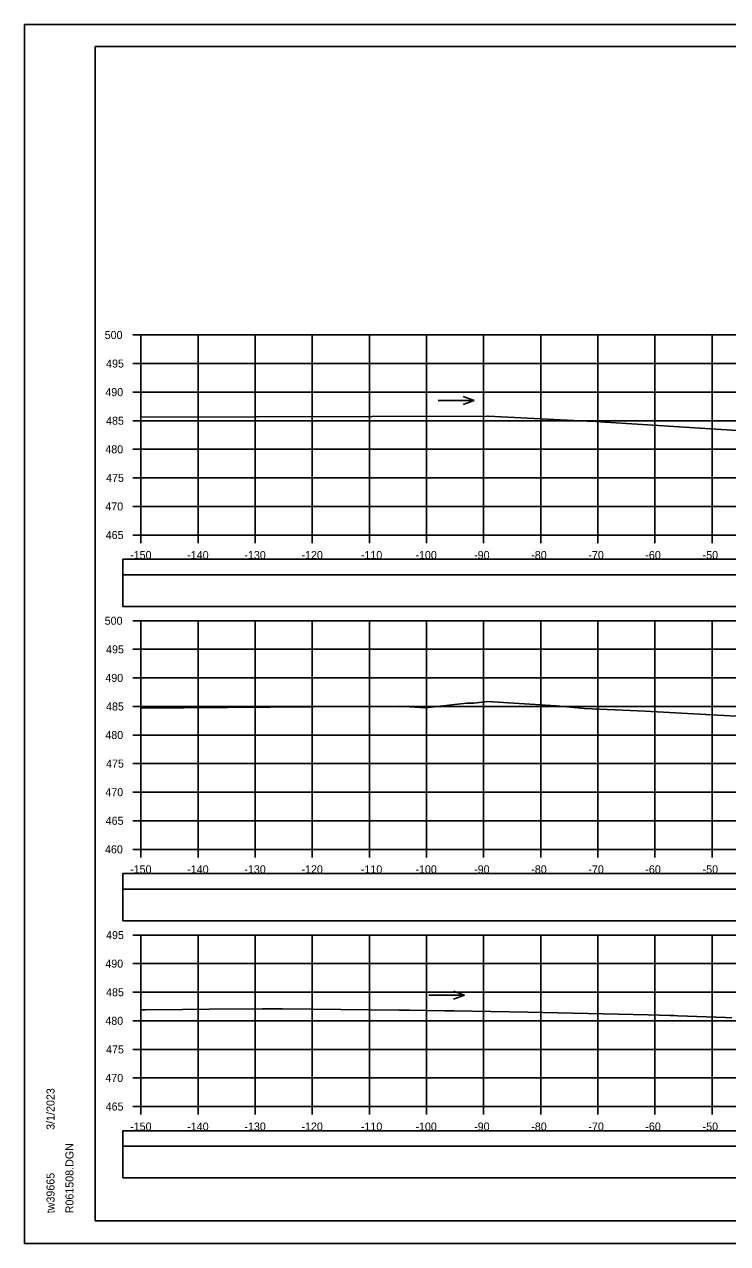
# Model space of a CAD drawing. Extents: x 1371057 to 1372761, y 380005 to 390517.
# Drawn here: x 1371390.5 to 1371513.6, y 380431.8 to 380645.1 of the extents above; entities that cross this region are included whole.
import ezdxf

# ---------------------------------------------------------------- set-up
doc = ezdxf.new("R2010")
doc.units = 0
for name, color, linetype in [('R_Axis', 7, 'Continuous'), ('R_Axis Annot', 7, 'Continuous'), ('R_Border', 7, 'Continuous'), ('R_Detour', 7, 'Continuous'), ('R_Dimension', 7, 'Continuous'), ('R_Exist Surface', 7, 'Continuous'), ('R_Grid', 7, 'Continuous'), ('R_No Plot', 7, 'Continuous'), ('R_Water Annot', 7, 'Continuous')]:
    doc.layers.add(name, color=color, linetype=linetype)

msp = doc.modelspace()

# ---------------------------------------------------------------- linework, layer by layer
at = {"layer": 'R_Axis'}
for p, q in [((1371409.47, 380590.74), (1371410.87, 380590.74)), ((1371410.87, 380555.74), (1371410.87, 380590.74)), ((1371409.47, 380585.74), (1371410.87, 380585.74)), ((1371409.47, 380580.74), (1371410.87, 380580.74)), ((1371409.47, 380575.74), (1371410.87, 380575.74)), ((1371409.47, 380570.74), (1371410.87, 380570.74)), ((1371409.47, 380565.74), (1371410.87, 380565.74)), ((1371409.47, 380560.74), (1371410.87, 380560.74)), ((1371409.47, 380555.74), (1371410.87, 380555.74)), ((1371410.87, 380555.74), (1371710.87, 380555.74)), ((1371410.87, 380554.34), (1371410.87, 380555.74)), ((1371420.87, 380554.34), (1371420.87, 380555.74)), ((1371430.87, 380554.34), (1371430.87, 380555.74)), ((1371440.87, 380554.34), (1371440.87, 380555.74)), ((1371450.87, 380554.34), (1371450.87, 380555.74)), ((1371460.87, 380554.34), (1371460.87, 380555.74)), ((1371470.87, 380554.34), (1371470.87, 380555.74)), ((1371480.87, 380554.34), (1371480.87, 380555.74)), ((1371490.87, 380554.34), (1371490.87, 380555.74)), ((1371500.87, 380554.34), (1371500.87, 380555.74)), ((1371510.87, 380554.34), (1371510.87, 380555.74)), ((1371409.47, 380540.74), (1371410.87, 380540.74)), ((1371410.87, 380500.74), (1371410.87, 380540.74)), ((1371409.47, 380535.74), (1371410.87, 380535.74)), ((1371409.47, 380530.74), (1371410.87, 380530.74)), ((1371409.47, 380525.74), (1371410.87, 380525.74)), ((1371409.47, 380520.74), (1371410.87, 380520.74)), ((1371409.47, 380515.74), (1371410.87, 380515.74)), ((1371409.47, 380510.74), (1371410.87, 380510.74)), ((1371409.47, 380505.74), (1371410.87, 380505.74)), ((1371409.47, 380500.74), (1371410.87, 380500.74)), ((1371410.87, 380500.74), (1371710.87, 380500.74)), ((1371410.87, 380499.34), (1371410.87, 380500.74)), ((1371420.87, 380499.34), (1371420.87, 380500.74)), ((1371430.87, 380499.34), (1371430.87, 380500.74)), ((1371440.87, 380499.34), (1371440.87, 380500.74)), ((1371450.87, 380499.34), (1371450.87, 380500.74)), ((1371460.87, 380499.34), (1371460.87, 380500.74)), ((1371470.87, 380499.34), (1371470.87, 380500.74)), ((1371480.87, 380499.34), (1371480.87, 380500.74)), ((1371490.87, 380499.34), (1371490.87, 380500.74)), ((1371500.87, 380499.34), (1371500.87, 380500.74)), ((1371510.87, 380499.34), (1371510.87, 380500.74)), ((1371409.47, 380485.74), (1371410.87, 380485.74)), ((1371410.87, 380455.74), (1371410.87, 380485.74)), ((1371409.47, 380480.74), (1371410.87, 380480.74)), ((1371409.47, 380475.74), (1371410.87, 380475.74)), ((1371409.47, 380470.74), (1371410.87, 380470.74)), ((1371409.47, 380465.74), (1371410.87, 380465.74)), ((1371409.47, 380460.74), (1371410.87, 380460.74)), ((1371409.47, 380455.74), (1371410.87, 380455.74)), ((1371410.87, 380455.74), (1371710.87, 380455.74)), ((1371410.87, 380454.34), (1371410.87, 380455.74)), ((1371420.87, 380454.34), (1371420.87, 380455.74)), ((1371430.87, 380454.34), (1371430.87, 380455.74)), ((1371440.87, 380454.34), (1371440.87, 380455.74)), ((1371450.87, 380454.34), (1371450.87, 380455.74)), ((1371460.87, 380454.34), (1371460.87, 380455.74)), ((1371470.87, 380454.34), (1371470.87, 380455.74)), ((1371480.87, 380454.34), (1371480.87, 380455.74)), ((1371490.87, 380454.34), (1371490.87, 380455.74)), ((1371500.87, 380454.34), (1371500.87, 380455.74)), ((1371510.87, 380454.34), (1371510.87, 380455.74))]:
    msp.add_line(p, q, dxfattribs=at)
at = {"layer": 'R_Border'}
for p, q in [((1371402.87, 380641.2), (1371719.05, 380641.2)), ((1371402.87, 380435.74), (1371402.87, 380641.2)), ((1371402.87, 380435.74), (1371402.87, 380435.74)), ((1371719.05, 380435.74), (1371402.87, 380435.74))]:
    msp.add_line(p, q, dxfattribs=at)
at = {"layer": 'R_Detour'}
for points in [[(1371407.72, 380548.78), (1371714.03, 380548.78), (1371714.03, 380551.49), (1371407.72, 380551.49)], [(1371407.72, 380493.78), (1371714.03, 380493.78), (1371714.03, 380496.49), (1371407.72, 380496.49)], [(1371407.72, 380448.78), (1371714.03, 380448.78), (1371714.03, 380451.49), (1371407.72, 380451.49)]]:
    msp.add_lwpolyline(points, close=True, dxfattribs=at)
at = {"layer": 'R_Dimension'}
for points in [[(1371407.72, 380543.26), (1371714.03, 380543.26), (1371714.03, 380548.78), (1371407.72, 380548.78)], [(1371407.72, 380488.26), (1371714.03, 380488.26), (1371714.03, 380493.78), (1371407.72, 380493.78)], [(1371407.72, 380443.26), (1371714.03, 380443.26), (1371714.03, 380448.78), (1371407.72, 380448.78)]]:
    msp.add_lwpolyline(points, close=True, dxfattribs=at)
at = {"layer": 'R_Exist Surface'}
for points in [[(1371410.87, 380576.35), (1371471.57, 380576.55), (1371471.64, 380576.56), (1371471.64, 380576.55), (1371488.92, 380575.69), (1371489.48, 380575.65), (1371515.19, 380574.03)], [(1371410.87, 380525.47), (1371456.22, 380525.78), (1371460.64, 380525.53), (1371467.92, 380526.31), (1371469.14, 380526.31), (1371471.03, 380526.53), (1371471.55, 380526.63), (1371483.58, 380525.83), (1371488.55, 380525.4), (1371499.14, 380524.91), (1371515.1, 380524.03)], [(1371410.87, 380472.66), (1371411.74, 380472.67), (1371418.14, 380472.74), (1371422.8, 380472.79), (1371432.16, 380472.86), (1371435.63, 380472.83), (1371456.12, 380472.61), (1371457.88, 380472.59), (1371464.04, 380472.49), (1371465.65, 380472.46), (1371478.62, 380472.26), (1371497.08, 380471.82), (1371499.7, 380471.77), (1371503.52, 380471.67), (1371504.29, 380471.64), (1371504.87, 380471.62), (1371513.22, 380471.33), (1371514.33, 380471.26)]]:
    msp.add_lwpolyline(points, dxfattribs=at)
at = {"layer": 'R_Grid'}
for p, q in [((1371410.87, 380590.74), (1371710.87, 380590.74)), ((1371410.87, 380555.74), (1371410.87, 380590.74)), ((1371420.87, 380555.74), (1371420.87, 380590.74)), ((1371430.87, 380555.74), (1371430.87, 380590.74)), ((1371440.87, 380555.74), (1371440.87, 380590.74)), ((1371450.87, 380555.74), (1371450.87, 380590.74)), ((1371460.87, 380555.74), (1371460.87, 380590.74)), ((1371470.87, 380555.74), (1371470.87, 380590.74)), ((1371480.87, 380555.74), (1371480.87, 380590.74)), ((1371490.87, 380555.74), (1371490.87, 380590.74)), ((1371500.87, 380555.74), (1371500.87, 380590.74)), ((1371510.87, 380555.74), (1371510.87, 380590.74)), ((1371410.87, 380585.74), (1371710.87, 380585.74)), ((1371410.87, 380580.74), (1371710.87, 380580.74)), ((1371410.87, 380575.74), (1371710.87, 380575.74)), ((1371410.87, 380570.74), (1371710.87, 380570.74)), ((1371410.87, 380565.74), (1371710.87, 380565.74)), ((1371410.87, 380560.74), (1371710.87, 380560.74)), ((1371410.87, 380555.74), (1371710.87, 380555.74)), ((1371410.87, 380540.74), (1371710.87, 380540.74)), ((1371410.87, 380500.74), (1371410.87, 380540.74)), ((1371420.87, 380500.74), (1371420.87, 380540.74)), ((1371430.87, 380500.74), (1371430.87, 380540.74)), ((1371440.87, 380500.74), (1371440.87, 380540.74)), ((1371450.87, 380500.74), (1371450.87, 380540.74)), ((1371460.87, 380500.74), (1371460.87, 380540.74)), ((1371470.87, 380500.74), (1371470.87, 380540.74)), ((1371480.87, 380500.74), (1371480.87, 380540.74)), ((1371490.87, 380500.74), (1371490.87, 380540.74)), ((1371500.87, 380500.74), (1371500.87, 380540.74)), ((1371510.87, 380500.74), (1371510.87, 380540.74)), ((1371410.87, 380535.74), (1371710.87, 380535.74)), ((1371410.87, 380530.74), (1371710.87, 380530.74)), ((1371410.87, 380525.74), (1371710.87, 380525.74)), ((1371410.87, 380520.74), (1371710.87, 380520.74)), ((1371410.87, 380515.74), (1371710.87, 380515.74)), ((1371410.87, 380510.74), (1371710.87, 380510.74)), ((1371410.87, 380505.74), (1371710.87, 380505.74)), ((1371410.87, 380500.74), (1371710.87, 380500.74)), ((1371410.87, 380485.74), (1371710.87, 380485.74)), ((1371410.87, 380455.74), (1371410.87, 380485.74)), ((1371420.87, 380455.74), (1371420.87, 380485.74)), ((1371430.87, 380455.74), (1371430.87, 380485.74)), ((1371440.87, 380455.74), (1371440.87, 380485.74)), ((1371450.87, 380455.74), (1371450.87, 380485.74)), ((1371460.87, 380455.74), (1371460.87, 380485.74)), ((1371470.87, 380455.74), (1371470.87, 380485.74)), ((1371480.87, 380455.74), (1371480.87, 380485.74)), ((1371490.87, 380455.74), (1371490.87, 380485.74)), ((1371500.87, 380455.74), (1371500.87, 380485.74)), ((1371510.87, 380455.74), (1371510.87, 380485.74)), ((1371410.87, 380480.74), (1371710.87, 380480.74)), ((1371410.87, 380475.74), (1371710.87, 380475.74)), ((1371410.87, 380470.74), (1371710.87, 380470.74)), ((1371410.87, 380465.74), (1371710.87, 380465.74)), ((1371410.87, 380460.74), (1371710.87, 380460.74)), ((1371410.87, 380455.74), (1371710.87, 380455.74))]:
    msp.add_line(p, q, dxfattribs=at)
at = {"layer": 'R_No Plot'}
for p, q in [((1371390.47, 380645.09), (1371723.8, 380645.09)), ((1371390.47, 380431.76), (1371723.8, 380431.76))]:
    msp.add_line(p, q, dxfattribs=at)
for points in [[(1371390.46, 380645.09), (1371723.8, 380645.09), (1371723.8, 380431.75), (1371390.46, 380431.75)], [(1371636.79, 380641.2), (1371656.41, 380641.2), (1371656.41, 380631.32), (1371672.52, 380631.32), (1371695.72, 380631.32), (1371695.84, 380603.16), (1371719.05, 380603.16), (1371719.05, 380435.74), (1371402.87, 380435.74), (1371402.87, 380641.2)]]:
    msp.add_lwpolyline(points, close=True, dxfattribs=at)
at = {"layer": 'R_Water Annot'}
for p, q in [((1371469.19, 380579.25), (1371467.27, 380579.95)), ((1371462.91, 380579.25), (1371469.19, 380579.25)), ((1371469.19, 380579.25), (1371467.27, 380578.55)), ((1371461.26, 380475.24), (1371467.55, 380475.24)), ((1371467.55, 380475.24), (1371465.62, 380475.94)), ((1371467.55, 380475.24), (1371465.62, 380474.54))]:
    msp.add_line(p, q, dxfattribs=at)

# ---------------------------------------------------------------- texts
at = {"layer": 'R_Axis Annot'}
for s, p in [('500', (1371404.53, 380590.04)), ('495', (1371404.77, 380585.04)), ('490', (1371404.64, 380580.04)), ('485', (1371404.77, 380575.04)), ('480', (1371404.64, 380570.04)), ('475', (1371404.77, 380565.04)), ('470', (1371404.64, 380560.04)), ('465', (1371404.7, 380555.04)), ('-150', (1371408.98, 380551.54)), ('-140', (1371418.98, 380551.54)), ('-130', (1371428.98, 380551.54)), ('-120', (1371438.98, 380551.54)), ('-110', (1371449.38, 380551.54)), ('-100', (1371458.93, 380551.54)), ('-90', (1371469.21, 380551.54)), ('-80', (1371479.21, 380551.54)), ('-70', (1371489.21, 380551.54)), ('-60', (1371499.18, 380551.54)), ('-50', (1371509.21, 380551.54)), ('500', (1371404.53, 380540.04)), ('495', (1371404.77, 380535.04)), ('490', (1371404.64, 380530.04)), ('485', (1371404.77, 380525.04)), ('480', (1371404.64, 380520.04)), ('475', (1371404.77, 380515.04)), ('470', (1371404.64, 380510.04)), ('465', (1371404.7, 380505.04)), ('460', (1371404.58, 380500.04)), ('-150', (1371408.98, 380496.54)), ('-140', (1371418.98, 380496.54)), ('-130', (1371428.98, 380496.54)), ('-120', (1371438.98, 380496.54)), ('-110', (1371449.38, 380496.54)), ('-100', (1371458.93, 380496.54)), ('-90', (1371469.21, 380496.54)), ('-80', (1371479.21, 380496.54)), ('-70', (1371489.21, 380496.54)), ('-60', (1371499.18, 380496.54)), ('-50', (1371509.21, 380496.54)), ('495', (1371404.77, 380485.04)), ('490', (1371404.64, 380480.04)), ('485', (1371404.77, 380475.04)), ('480', (1371404.64, 380470.04)), ('475', (1371404.77, 380465.04)), ('470', (1371404.64, 380460.04)), ('465', (1371404.7, 380455.04)), ('-150', (1371408.98, 380451.54)), ('-140', (1371418.98, 380451.54)), ('-130', (1371428.98, 380451.54)), ('-120', (1371438.98, 380451.54)), ('-110', (1371449.38, 380451.54)), ('-100', (1371458.93, 380451.54)), ('-90', (1371469.21, 380451.54)), ('-80', (1371479.21, 380451.54)), ('-70', (1371489.21, 380451.54)), ('-60', (1371499.18, 380451.54)), ('-50', (1371509.21, 380451.54))]:
    msp.add_text(s, height=1.4, dxfattribs=at).set_placement(p)
at = {"layer": 'R_Border'}
for s, p in [('3/1/2023', (1371395.74, 380451.66)), ('R061508.DGN', (1371399.06, 380437.06)), ('tw39665', (1371395.74, 380437.06))]:
    msp.add_text(s, height=1.4, rotation=90, dxfattribs=at).set_placement(p)

doc.saveas('drawing.dxf')
